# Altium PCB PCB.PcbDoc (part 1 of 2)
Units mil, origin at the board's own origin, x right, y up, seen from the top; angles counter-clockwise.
Board outline 5216.54 x 1820.87 mil, 2 copper layers (Top Layer, Bottom Layer), stack 62 mil thick; 55 components, 32 nets, 136 pads, 25 vias.
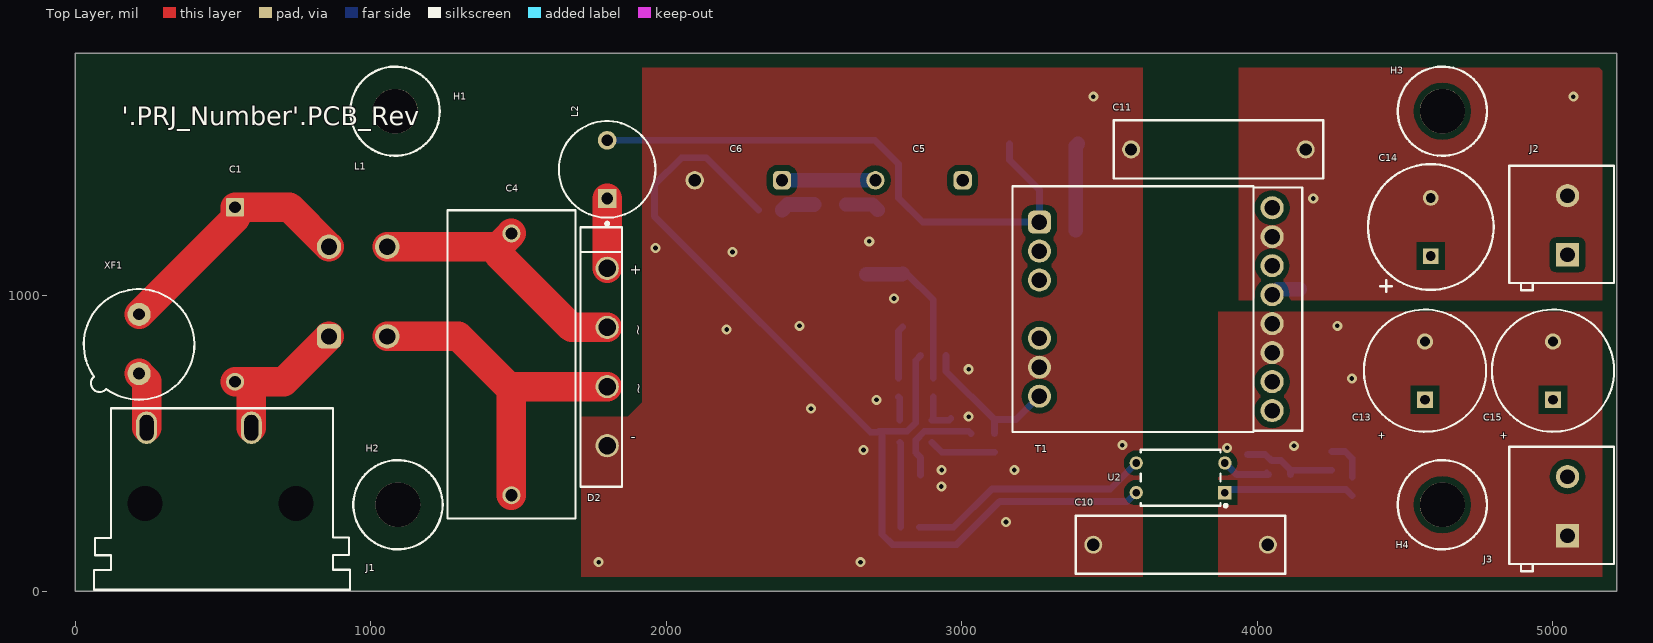
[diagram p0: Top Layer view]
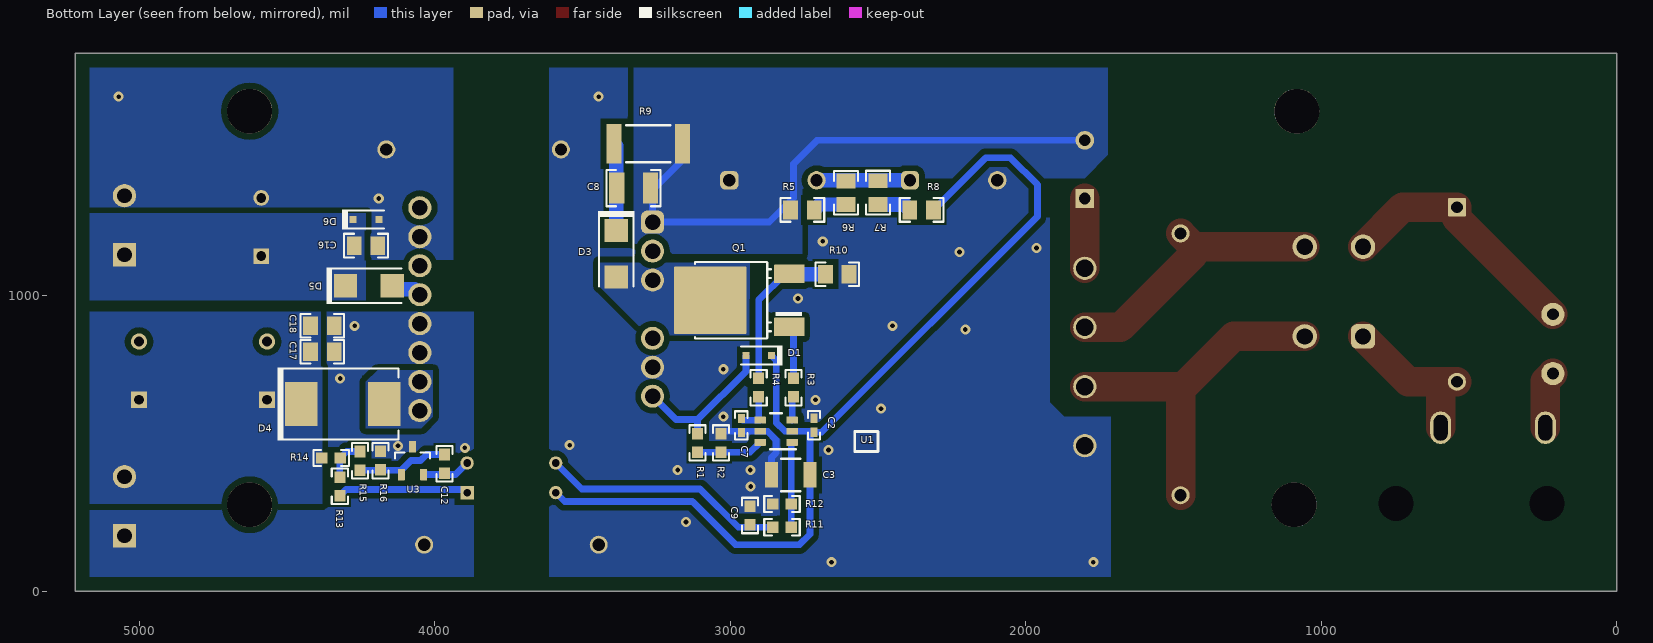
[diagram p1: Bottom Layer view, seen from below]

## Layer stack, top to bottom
Top Solder: solder mask 0.4, Solder Resist, Dk 3.5
Top Layer: signal copper 1.4
Dielectric1: core 59.2, FR-4, Dk 4.8
Bottom Layer: signal copper 1.4
Bottom Solder: solder mask 0.4, Solder Resist, Dk 3.5

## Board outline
0,0 5216.54,0 5216.54,1820.87 0,1820.87

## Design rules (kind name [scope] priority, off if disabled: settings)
AcuteAngle [All] p1: minimum=4.50000000000000E+0001 checktracksonly=FALSE
AssemblyTestPointUsage [All] p1: valid=2
Clearance Clearance_2 [InNetClass('HV') vs Not InNetClass('HV')] p1: gap=60 ignorepadtopadclearanceinfootprint=FALSE
Clearance Clearance_1 [InNetClass('MV') vs Not InNetClass('MV')] p2: gap=30 ignorepadtopadclearanceinfootprint=FALSE
Clearance Clearance_Keepouts [((IsTrack Or IsArc) And Not InPoly) And IsFree and IsKeepOut vs ((IsTrack Or IsArc) And Not InPoly) And IsFree and IsKeepOut] p3: gap=0 ignorepadtopadclearanceinfootprint=FALSE
Clearance Clearance_BoardEdge_MountingHoles [OnCopper and InComponentClass('Mounting Holes') vs IsKeepOut] p4: gap=40 ignorepadtopadclearanceinfootprint=FALSE except(0: Arc-Hole Track-Hole SMDPad-Hole THPad-Hole Via-Hole Fill-Hole Poly-Hole Region-Hole Text-Hole)
Clearance Clearance_BoardEdge_Poly [OnCopper and InPoly vs IsKeepOut] p5: gap=50 ignorepadtopadclearanceinfootprint=FALSE except(0: Arc-Hole Track-Hole SMDPad-Hole THPad-Hole Via-Hole Fill-Hole Poly-Hole Region-Hole Text-Hole)
Clearance Clearance_BoardEdge [OnCopper and Not InComponentClass('Logo') and not InComponentClass('FiducialMark') and not InRegion(1000,500,4000,800) and Not IsKeepout vs IsKeepOut] p6: gap=75 ignorepadtopadclearanceinfootprint=FALSE except(0: Arc-Hole Track-Hole SMDPad-Hole THPad-Hole Via-Hole Fill-Hole Poly-Hole Region-Hole Text-Hole)
Clearance Clearance_Poly [InPolygon] p7: gap=20 ignorepadtopadclearanceinfootprint=FALSE except(0: Arc-Hole Track-Hole SMDPad-Hole THPad-Hole Via-Hole Fill-Hole Poly-Hole Region-Hole Text-Hole)
Clearance [All] p8: gap=7.87 ignorepadtopadclearanceinfootprint=FALSE except(0: Arc-Hole Track-Hole SMDPad-Hole THPad-Hole Via-Hole Fill-Hole Poly-Hole Region-Hole Text-Hole)
ComponentClearance ComponentClearance_MountingHoles_FiducialMarks [InComponentClass('Mounting Holes') vs InComponentClass('FiducialMark')] p1: gap=20 collisioncheckmode=3 verticalgap=10 showdistances=FALSE
ComponentClearance ComponentClearance_Shunt [InComponentClass('Header') vs InComponentClass('Shunt')] p2: gap=0 collisioncheckmode=3 verticalgap=0 showdistances=FALSE
ComponentClearance ComponentClearance_Logo [InComponentClass('Logo')] p3: gap=5 collisioncheckmode=3 verticalgap=10 showdistances=FALSE
ComponentClearance ComponentClearance_ScrewToNut [(HasFootprint('NY PMS 440 0025 PH')) vs (HasFootprint('Keystone_1902C'))] p4: gap=20 collisioncheckmode=3 verticalgap=100000 showdistances=FALSE
ComponentClearance ComponentClearance_MountingHoles [InComponentClass('Mounting Holes')] p5: gap=20 collisioncheckmode=3 verticalgap=10 showdistances=FALSE
ComponentClearance ComponentClearance_SmallPassives [HasFootprint('0201*') or HasFootprint('0402*') or HasFootprint('0508') or HasFootprint('0603*') or HasFootprint('0612') or HasFootprint('0805*') or HasFootprint('0815*') or HasFootprint('0830*') or HasFootprint('1206*') or HasFootprint('1210*') or HasFootprint('1808*') or HasFootprint('1812*') or HasFootprint('1825*') or HasFootprint('2010*') or HasFootprint('2220*') or HasFootprint('2225*') or HasFootprint('2512*') or HasFootprint('2728*') or HasFootprint('3518*') vs HasFootprint('0201*') or HasFootprint('0402*') or HasFootprint('0508') or HasFootprint('0603*') or HasFootprint('0612') or HasFootprint('0805*') or HasFootprint('0815*') or HasFootprint('0830*') or HasFootprint('1206*') or HasFootprint('1210*') or HasFootprint('1808*') or HasFootprint('1812*') or HasFootprint('1825*') or HasFootprint('2010*') or HasFootprint('2220*') or HasFootprint('2225*') or HasFootprint('2512*') or HasFootprint('2728*') or HasFootprint('3518*')] p6: gap=20 collisioncheckmode=3 verticalgap=20 showdistances=FALSE
ComponentClearance ComponentClearance_THtoSMT [IsThruComponent vs IsSMTComponent] p7: gap=10 collisioncheckmode=3 verticalgap=10 showdistances=FALSE
ComponentClearance ComponentClearance_THtoTH [IsThruComponent vs IsThruComponent] p8: gap=10 collisioncheckmode=3 verticalgap=10 showdistances=FALSE
ComponentClearance [All] p9: gap=10 collisioncheckmode=3 verticalgap=10 showdistances=FALSE
DiffPairsRouting [All] p1: maxlimit=100 minlimit=10 mostfreqgap=10 toplayer_minwidth=15 toplayer_maxwidth=15 toplayer_prefwidth=15 bottomlayer_minwidth=15 bottomlayer_maxwidth=15 bottomlayer_prefwidth=15 maxuncoupledlength=1000
FabricationTestPointUsage TestPointUsage [All] p1: valid=2 allowmultiple=FALSE
FabricationTestpoint Testpoint [All] p1: side=3 testpointundercomponent=TRUE minsize=40 maxsize=100 preferedsize=60 minholesize=0 maxholesize=40 preferedholesize=32 testpointgrid=1 allowsidetop=TRUE allowsidebottom=TRUE usegrid=TRUE gridtolerance=0.01
FanoutControl Fanout_LCC [IsLCC] p1: bgadir=Out bgaviamode=Centered fanoutstyle=Auto fanoutdirection=Alternating viagrid=1 // Fanout_LCC (Default Rule)
FanoutControl Fanout_BGA [IsBGA] p2: bgadir=Out bgaviamode=Centered fanoutstyle=Auto fanoutdirection=Alternating viagrid=1 // Fanout_BGA (Default Rule)
FanoutControl Fanout_Default [All] p4: bgadir=Out bgaviamode=Centered fanoutstyle=Auto fanoutdirection=Alternating viagrid=1 // Fanout_Default (Default Rule)
FanoutControl Fanout_Small [(CompPinCount < 5)] p5: bgadir=Out bgaviamode=Centered fanoutstyle=Auto fanoutdirection=OutThenIn viagrid=1 // Fanout_Small (Default Rule)
Height [All] p1: minheight=0 maxheight=3000 prefheight=500
HoleSize [All] p1: absolutevalues=TRUE maxlimit=251 minlimit=7 maxpercent=80.000 minpercent=20.000
MinimumAnnularRing MinimumAnnularRing_ThermalPadVias [IsVia and InAnyComponent] p1: minimumring=5.91
MinimumAnnularRing [All] p2: minimumring=4.9
MinimumSolderMaskSliver MinimumSolderMaskSliver_Logo [InComponentClass('Logo') vs InComponentClass('Logo')] p1: minsoldermaskwidth=0.7
MinimumSolderMaskSliver [All] p2: minsoldermaskwidth=2
PlaneConnect [All] p1: planeconnectstyle=Direct reliefexpansion=10 reliefentries=4 reliefconductorwidth=10 reliefairgap=10
PolygonConnect PolygonConnect_15 [All vs IsNamedPolygon('C109_2') Or  IsNamedPolygon('C107_2') Or  IsNamedPolygon('HV') Or  IsNamedPolygon('Q203_5') Or  IsNamedPolygon('C107_2') Or  IsNamedPolygon('HS') Or  IsNamedPolygon('Q201_5') Or  IsNamedPolygon('Q203_5') Or  IsNamedPolygon('C106_2') Or  IsNamedPolygon('C108_2') Or  IsNamedPolygon('Vout') Or  IsNamedPolygon('Q203_5') Or  IsNamedPolygon('C108_2') Or  IsNamedPolygon('C113_2') Or  IsNamedPolygon('Q203_5') Or  IsNamedPolygon('Q201_5') Or  IsNamedPolygon('C107_2') Or  IsNamedPolygon('C102_1') Or  IsNamedPolygon('SGND') Or  IsNamedPolygon('GND') Or  IsNamedPolygon('SGND') Or  IsNamedPolygon('GND') Or  IsNamedPolygon('IN+') Or  IsNamedPolygon('IN+') Or  IsNamedPolygon('Q201_5') Or  IsNamedPolygon('Q201_5') Or  IsNamedPolygon('SGND') Or  IsNamedPolygon('SGND') Or  IsNamedPolygon('Vout') Or  IsNamedPolygon('Vout') Or  IsNamedPolygon('IN+') Or  IsNamedPolygon('GND') Or  IsNamedPolygon('IN+') Or  IsNamedPolygon('GND')] p1: connectstyle=Direct reliefconductorwidth=10 reliefentries=4 polygonreliefangle="90 Angle" airgapwidth=10
PolygonConnect PolygonConnect_14 [All vs IsNamedPolygon('C106_2') Or  IsNamedPolygon('C107_2') Or  IsNamedPolygon('C107_2') Or  IsNamedPolygon('C107_2') Or  IsNamedPolygon('C102_1') Or  IsNamedPolygon('Q203_5') Or  IsNamedPolygon('Vout') Or  IsNamedPolygon('Q203_5') Or  IsNamedPolygon('Q203_5') Or  IsNamedPolygon('Q201_5') Or  IsNamedPolygon('C108_2') Or  IsNamedPolygon('Q203_5') Or  IsNamedPolygon('HS') Or  IsNamedPolygon('HV') Or  IsNamedPolygon('C108_2') Or  IsNamedPolygon('Q201_5') Or  IsNamedPolygon('C109_2') Or  IsNamedPolygon('Q201_5') Or  IsNamedPolygon('Q201_5') Or  IsNamedPolygon('C113_2')] p2: connectstyle=Direct reliefconductorwidth=10 reliefentries=4 polygonreliefangle="90 Angle" airgapwidth=10
PolygonConnect PolygonConnect_13 [All vs IsNamedPolygon('C102_1') Or  IsNamedPolygon('HV') Or  IsNamedPolygon('C107_2') Or  IsNamedPolygon('C109_2') Or  IsNamedPolygon('C107_2') Or  IsNamedPolygon('C108_2') Or  IsNamedPolygon('C106_2') Or  IsNamedPolygon('C108_2') Or  IsNamedPolygon('C113_2') Or  IsNamedPolygon('C107_2')] p3: connectstyle=Direct reliefconductorwidth=10 reliefentries=4 polygonreliefangle="90 Angle" airgapwidth=10
PolygonConnect PolygonConnect_12 [All vs IsNamedPolygon('C107_2') Or  IsNamedPolygon('C113_2') Or  IsNamedPolygon('C106_2') Or  IsNamedPolygon('C107_2') Or  IsNamedPolygon('C107_2') Or  IsNamedPolygon('C102_1')] p4: connectstyle=Direct reliefconductorwidth=10 reliefentries=4 polygonreliefangle="90 Angle" airgapwidth=10
PolygonConnect PolygonConnect_11 [All vs IsNamedPolygon('C106_2') Or  IsNamedPolygon('C102_1') Or  IsNamedPolygon('C107_2') Or  IsNamedPolygon('C107_2') Or  IsNamedPolygon('C107_2')] p5: connectstyle=Direct reliefconductorwidth=10 reliefentries=4 polygonreliefangle="90 Angle" airgapwidth=10
PolygonConnect PolygonConnect_10 [All vs IsNamedPolygon('C106_2')] p6: connectstyle=Direct reliefconductorwidth=10 reliefentries=4 polygonreliefangle="90 Angle" airgapwidth=10
PolygonConnect PolygonConnect_9 [All vs IsNamedPolygon('C11_1') Or  IsNamedPolygon('Vin') Or  IsNamedPolygon('Vin') Or  IsNamedPolygon('5V') Or  IsNamedPolygon('D6_2') Or  IsNamedPolygon('Q3_3') Or  IsNamedPolygon('GND2') Or  IsNamedPolygon('GND2') Or  IsNamedPolygon('GND') Or  IsNamedPolygon('Q3_4') Or  IsNamedPolygon('12V5') Or  IsNamedPolygon('GND') Or  IsNamedPolygon('12V5') Or  IsNamedPolygon('D3_1')] p7: connectstyle=Direct reliefconductorwidth=10 reliefentries=4 polygonreliefangle="90 Angle" airgapwidth=10
PolygonConnect PolygonConnect_8 [All vs IsNamedPolygon('C11_1') Or  IsNamedPolygon('Vin') Or  IsNamedPolygon('12V5') Or  IsNamedPolygon('Q3_3') Or  IsNamedPolygon('GND2') Or  IsNamedPolygon('GND2') Or  IsNamedPolygon('5V') Or  IsNamedPolygon('Q3_4') Or  IsNamedPolygon('12V5')] p8: connectstyle=Direct reliefconductorwidth=10 reliefentries=4 polygonreliefangle="90 Angle" airgapwidth=10
PolygonConnect PolygonConnect_7 [All vs IsNamedPolygon('GND2') Or  IsNamedPolygon('GND2') Or  IsNamedPolygon('5V') Or  IsNamedPolygon('12V5') Or  IsNamedPolygon('12V5') Or  IsNamedPolygon('C11_1')] p9: connectstyle=Direct reliefconductorwidth=10 reliefentries=4 polygonreliefangle="90 Angle" airgapwidth=10
PolygonConnect PolygonConnect_6 [All vs IsNamedPolygon('GND2') Or  IsNamedPolygon('SGND') Or  IsNamedPolygon('GND1') Or  IsNamedPolygon('C901_1') Or  IsNamedPolygon('SGND') Or  IsNamedPolygon('GND2') Or  IsNamedPolygon('GND1')] p10: connectstyle=Direct reliefconductorwidth=10 reliefentries=4 polygonreliefangle="90 Angle" airgapwidth=10
PolygonConnect PolygonConnect_5 [All vs IsNamedPolygon('GND1') Or  IsNamedPolygon('GND1')] p11: connectstyle=Direct reliefconductorwidth=10 reliefentries=4 polygonreliefangle="90 Angle" airgapwidth=10
PolygonConnect PolygonConnect_4 [All vs IsNamedPolygon('C21_1') Or  IsNamedPolygon('C5_1') Or  IsNamedPolygon('C12_2') Or  IsNamedPolygon('C2_2') Or  IsNamedPolygon('C13_1') Or  IsNamedPolygon('C28_1') Or  IsNamedPolygon('C6_1') Or  IsNamedPolygon('GND') Or  IsNamedPolygon('GND2') Or  IsNamedPolygon('C14_1') Or  IsNamedPolygon('C13_1') Or  IsNamedPolygon('Q1_3') Or  IsNamedPolygon('C14_1') Or  IsNamedPolygon('C5_1') Or  IsNamedPolygon('GND2') Or  IsNamedPolygon('C28_1') Or  IsNamedPolygon('D5_2') Or  IsNamedPolygon('D6_2') Or  IsNamedPolygon('D2_1') Or  IsNamedPolygon('C12_2') Or  IsNamedPolygon('D2_1') Or  IsNamedPolygon('C4_1') Or  IsNamedPolygon('C4_1') Or  IsNamedPolygon('C2_2') Or  IsNamedPolygon('GND') Or  IsNamedPolygon('C33_1') Or  IsNamedPolygon('C9_1')] p12: connectstyle=Direct reliefconductorwidth=10 reliefentries=4 polygonreliefangle="90 Angle" airgapwidth=10
PolygonConnect PolygonConnect_3 [All vs IsNamedPolygon('C28_1') Or  IsNamedPolygon('C12_2') Or  IsNamedPolygon('C28_1') Or  IsNamedPolygon('C9_1') Or  IsNamedPolygon('D5_2') Or  IsNamedPolygon('C12_2') Or  IsNamedPolygon('C2_2') Or  IsNamedPolygon('C14_1') Or  IsNamedPolygon('C4_1') Or  IsNamedPolygon('C14_1') Or  IsNamedPolygon('D6_2') Or  IsNamedPolygon('GND2') Or  IsNamedPolygon('Q1_3') Or  IsNamedPolygon('C5_1') Or  IsNamedPolygon('D2_1') Or  IsNamedPolygon('C4_1') Or  IsNamedPolygon('C13_1') Or  IsNamedPolygon('C5_1') Or  IsNamedPolygon('C13_1') Or  IsNamedPolygon('C33_1') Or  IsNamedPolygon('D2_1') Or  IsNamedPolygon('GND') Or  IsNamedPolygon('GND') Or  IsNamedPolygon('GND2') Or  IsNamedPolygon('C2_2') Or  IsNamedPolygon('C6_1') Or  IsNamedPolygon('C21_1')] p13: connectstyle=Direct reliefconductorwidth=10 reliefentries=4 polygonreliefangle="90 Angle" airgapwidth=10
PolygonConnect PolygonConnect_2 [All vs IsNamedPolygon('C21_1') Or  IsNamedPolygon('C4_1') Or  IsNamedPolygon('D5_2') Or  IsNamedPolygon('C5_1') Or  IsNamedPolygon('C14_1') Or  IsNamedPolygon('C13_1') Or  IsNamedPolygon('C4_1') Or  IsNamedPolygon('C33_1') Or  IsNamedPolygon('C12_2') Or  IsNamedPolygon('D2_1') Or  IsNamedPolygon('C2_2') Or  IsNamedPolygon('C28_1') Or  IsNamedPolygon('C12_2') Or  IsNamedPolygon('D2_1') Or  IsNamedPolygon('C5_1') Or  IsNamedPolygon('Q1_3') Or  IsNamedPolygon('GND') Or  IsNamedPolygon('D6_2') Or  IsNamedPolygon('C6_1') Or  IsNamedPolygon('C2_2') Or  IsNamedPolygon('C14_1') Or  IsNamedPolygon('C28_1') Or  IsNamedPolygon('C13_1') Or  IsNamedPolygon('C9_1') Or  IsNamedPolygon('GND')] p14: connectstyle=Direct reliefconductorwidth=10 reliefentries=4 polygonreliefangle="90 Angle" airgapwidth=10
PolygonConnect PolygonConnect_1 [All vs IsNamedPolygon('C28_1') Or  IsNamedPolygon('D5_2') Or  IsNamedPolygon('C5_1') Or  IsNamedPolygon('C5_1') Or  IsNamedPolygon('D2_1') Or  IsNamedPolygon('C21_1') Or  IsNamedPolygon('C9_1') Or  IsNamedPolygon('C4_1') Or  IsNamedPolygon('C14_1') Or  IsNamedPolygon('C28_1') Or  IsNamedPolygon('C6_1') Or  IsNamedPolygon('C12_2') Or  IsNamedPolygon('C33_1') Or  IsNamedPolygon('C4_1') Or  IsNamedPolygon('C13_1') Or  IsNamedPolygon('C12_2') Or  IsNamedPolygon('D6_2') Or  IsNamedPolygon('C2_2') Or  IsNamedPolygon('C14_1') Or  IsNamedPolygon('D2_1') Or  IsNamedPolygon('C2_2') Or  IsNamedPolygon('C13_1')] p15: connectstyle=Direct reliefconductorwidth=10 reliefentries=4 polygonreliefangle="90 Angle" airgapwidth=10
PolygonConnect [All] p16: connectstyle=Direct reliefconductorwidth=10 reliefentries=4 polygonreliefangle="90 Angle" airgapwidth=10
RoutingVias ThermalPadVias [IsVia and InAnyComponent] p1: holewidth=7.87 width=19.68 viastyle="Through Hole" minholewidth=7.87 minwidth=19.68 maxholewidth=12.99 maxwidth=23.62
RoutingVias [All] p2: holewidth=16 width=34 viastyle="Through Hole" minholewidth=7.87 minwidth=20 maxholewidth=40 maxwidth=65
SilkToBoardRegionClearance [Not ((IsComment or IsDesignator) And (Hide <> 'False')) and not InRegion(1000,500,4000,800)] p1:
SilkToSilkClearance SilkToSilkClearance_Pb-FreeLogo [(HasFootprint('Pb-Free_Overlay_Medium') OR HasFootprint('Pb-Free_Overlay_Small')) vs (HasFootprint('Pb-Free_Overlay_Medium') OR HasFootprint('Pb-Free_Overlay_Small'))] p1: silktosilkclearance=0
SilkToSilkClearance [All] p2: silktosilkclearance=1
SilkToSolderMaskClearance "Silk to Solder Mask Opening" [All] p1: minsilkscreentomaskgap=1 clearancetoexposedcopper=FALSE
SolderMaskExpansion [All] p1: expansion=1.97
Width [All] p1: maxlimit=100 minlimit=6 preferedwidth=10 checkconnectedcopper=TRUE
14 further rules are at their usual default settings.

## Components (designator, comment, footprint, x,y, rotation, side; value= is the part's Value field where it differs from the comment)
C1 "B32642B0223J" FP-B32642B0223J_RADIAL-MFG 541.34,1003.94 r270 top value=0.022µF
C2 "GCM155R71H104KE02D" 0402 2716.54,561.74 r90 bottom value=0.1uF
C3 "C1210C226K3RAC7800" 1210_280 2795.28,393.7 r0 bottom value=22uF
C4 "B32653A224J189" B32653_2650x2050x1100 1476.38,767.72 r90 top value=0.22uF
C5 "400BXW68MEFR14.5X30" BXW_1450x3000_HU 2855.32,1390.38 r180 top value=68uF
C6 "400BXW68MEFR14.5X30" BXW_1450x3000_HU 2244.09,1390.38 r180 top value=68uF
C7 "GRM1555C1H270JA01D" 0402 2962.6,561.02 r270 bottom value=27pF
C8 "VJ1210Y472KXGAT5Z" 1210 3326.77,1364.15 r0 bottom value=4700pF
C9 "GRM188R71H221KA01D" 0603 2933.07,256.27 r90 bottom value=220pF
C10 "B32652A0103K" B32652A_500x1050x1800 3740.16,157.48 r180 top value=0.01uF
C11 "B32652A0103K" B32652A_500x1050x1800 3868.11,1494.86 r180 top value=0.01uF
C12 "GRM188R71E153KA01D" 0603 3966.53,431.27 r270 bottom value=0.015uF
C13 "6.3ZLJ2700M10X20" ZLJ_1000X2000 4566.93,746.23 r90 top value=2700uF
C14 "25ZLJ470M10X12.5" ZLJ_1000x1250 4586.61,1232.26 r90 top value=470uF
C15 "6.3ZLJ2700M10X20" ZLJ_1000X2000 5000,746.23 r90 top value=2700uF
C16 "B37941K9105K62" 0805_HV 4232.28,1169.46 r180 bottom value=1uF
C17 "B37941K9105K62" 0805_HV 4379.92,810.43 r180 bottom value=1uF
C18 "B37941K9105K62" 0805_HV 4379.92,898.17 r180 bottom value=1uF
D1 "BAS316,115" SOD-323 2903.54,797.24 r0 bottom value=100V
D2 "GBU4K-E3/51" GBU 1800.17,792.52 r270 top value=800V
D3 "US1K-13-F" SMA 3385.83,1141.73 r270 bottom value=800V
D4 "B3100-13-F" SMC 4311.02,633.26 r180 bottom value=100V
D5 "STPS1150A" SMA 4222.44,1033.46 r180 bottom value=150V
D6 "BZX384-C15,115" SOD-323 4232.28,1258.04 r180 bottom value=15V
H1 "4826" KEYSTONE_4826 1082.68,1624.02 r0 top
H2 "4826" KEYSTONE_4826 1092.52,292.69 r0 top
H3 "4826" KEYSTONE_4826 4625.98,1624.02 r0 top
H4 "4826" KEYSTONE_4826 4625.98,292.69 r0 top
J1 "770W-X2/10" CONN_AC_770W-SERIES 492.13,423.23 r180 top
J2 "ED120/2DS" On-Shore_ED120_2DS 5049.21,1238.36 r90 top
J3 "ED120/2DS" On-Shore_ED120_2DS 5049.21,287.77 r90 top
L1 "750318019" Wurth_750318019 957.52,1013.78 r90 top value=850uH
L2 "768772102" WE-TI_8095 1800.17,1427.17 r90 top value=1mH
Q1 "FQD2N100TM" DPAK 2933.88,984.25 r0 bottom value=1000V
R1 "CRCW060338K3FKEA" 0603 3110.24,501.75 r90 bottom value=38.3k
R2 "CRCW06036K04FKEA" 0603 3031.5,501.75 r270 bottom value=6.04k
R3 "CRCW060310R0FKEA" 0603 2785.43,688.96 r90 bottom value=10.0
R4 "CRCW0603787RFKEA" 0603 2903.54,688.96 r90 bottom value=787
R5 "CRCW0805470KJNEA" 0805_HV 2755.91,1289.98 r0 bottom value=470k
R6 "CRCW0805470KJNEA" 0805_HV 2608.27,1348.43 r270 bottom value=470k
R7 "CRCW0805470KJNEA" 0805_HV 2500,1348.74 r90 bottom value=470k
R8 "CRCW0805470KJNEA" 0805_HV 2352.36,1289.98 r0 bottom value=470k
R9 "CRCW25128K20JNEG" 2512 3277.19,1513.95 r180 bottom value=8.2k
R10 "RC0805FR-071R21L" 0805_HV 2637.8,1072.83 r0 bottom value=1.21
R11 "CRCW060378K7FKEA" 0603 2824.8,216.54 r0 bottom value=78.7k
R12 "CRCW06034K02FKEA" 0603 2824.8,295.28 r180 bottom value=4.02k
R13 "CRCW0603750RFKEA" 0603 4320.86,354.63 r90 bottom value=750
R14 "CRCW06030000Z0EA" 0603 4350.39,450.95 r0 bottom value=0
R15 "CRCW060390K9FKEA" 0603 4251.96,441.11 r90 bottom value=90.9k
R16 "CRCW060340K2FKEA" 0603 4183.07,441.97 r270 bottom value=40.2k
T1 "750317656" Wurth_EE20-10-6_5643 3656.32,954.31 r0 top
U1 "UCC28742DBVR" DBV0006A_N 2844.49,541.34 r0 bottom
U2 "FOD817A" DIP-4 3740.16,383.86 r180 top
U3 "TLV431ACDBZR" DBZ0003A_N 4074.8,441.97 r90 bottom
XF1 "56000001009" FuseHolder_560000010 216.54,836.61 r270 top value=TR5

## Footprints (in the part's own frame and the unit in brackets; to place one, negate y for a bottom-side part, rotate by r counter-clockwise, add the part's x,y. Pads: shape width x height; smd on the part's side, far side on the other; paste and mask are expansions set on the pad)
0402 [mm] "0402 from SM-752 data"
  rect 0.8x0.6 smd: 1(-0.6,0) 2(0.6,0)
  silkscreen extent -1.22,-0.52 1.22,0.52, body extent -0.55,-0.3 0.55,0.3, height 0.6
0603 [mm] "0603 from SM-752 data"
  rect 1x0.95 smd: 1(-0.8,0) 2(0.8,0)
  silkscreen extent -1.52,-0.69 1.52,0.69, body extent -0.87,-0.47 0.87,0.47, height 1
0805_HV [mil] "0805 with 30mil clearance between pads"
  rect 50x63 smd: 1(-40,0) 2(40,0)
  silkscreen extent -74,-40 74,40, body extent -43,-29 43,29, height 57
1210 [mm] "1210 from SM-752 data"
  rect 1.3x2.7 smd: 1(-1.45,0) 2(1.45,0)
  silkscreen extent -2.32,-1.57 2.32,1.57, body extent -1.7,-1.35 1.7,1.35, height 1.35
1210_280 [mm] "SMD, 2-Leads, Body 3.6x2.8mm, Height 2.8mm"
  rect 1.1x2.2 smd: 1(-1.65,0) 2(1.65,0)
  silkscreen extent -0.84,-1.4 0.84,1.4, body extent -1.8,-1.4 1.8,1.4, height 2.8
2512 [mm] "Chip Resistor, Body 6.3x3.2mm, IPC Medium Density"
  rect 1.3x3.4 smd: 1(-2.95,0) 2(2.95,0)
  silkscreen extent -1.9,-1.6 1.9,1.6, body extent -3.22,-1.67 3.22,1.67, height 0.71
B32652A_500x1050x1800 [mm] "THD, 2-Leads, Body 18x5mm, Height 10.5mm"
  round 1.55 hole 1.05: 1(-7.5,0) 2(7.5,0)
  silkscreen extent -9,-2.5 9,2.5, body extent -9,-2.5 9,2.5, height 10.5
B32653_2650x2050x1100 [mm] "TH, 2-Leads, Body 26.5x11mm, Pin Spacing 22.5mm"
  round 1.55 hole 1.05: 1(-11.25,0) 2(11.25,0)
  silkscreen extent -13.25,-5.5 13.25,5.5, body extent -13.25,-5.5 13.25,5.5, height 20.5
BXW_1450x3000_HU [mm] "TH, 2-Leads, Dia 14.5mm, Pin Spacing 7.5mm"
  rrect50% 1.575x1.575 hole 1.05: 1(-3.75,0)
  round 1.575 hole 1.05: 2(3.75,0)
  body extent -7.5,-0.4 7.5,34.55, height 15
CONN_AC_770W-SERIES [mm] "Qualtek Electronics"
  oval 1.8x2.8 hole 1.2 slot 2.2 at 90 deg: 1(6.35,-3.3) 2(-2.65,-3.3)
  round 2 hole 3 unplated: MH1(6.5,3.2) MH2(-6.5,3.2)
  silkscreen extent -11.12,-4.97 10.87,10.63, body extent -11.05,-4.8 10.8,10.6, height 22
DBV0006A_N [mm] "SOT23, 6-Leads, Body 2.9x1.6mm, Pitch 0.95mm, Lead Span 2.8mm, IPC Medium Density"
  rrect17% 1x0.6 smd: 1(-1.375,0.95) 2(-1.375,0) 3(-1.375,-0.95) 4(1.375,-0.95) 5(1.375,0) 6(1.375,0.95)
  silkscreen extent -1.68,-1.55 0.5,1.55, body extent -1.42,-1.46 1.42,1.46, height 1.12
DBZ0003A_N [mm] "SOT23, 3-Leads, Body 2.9x1.3mm, Pitch 0.95mm, Lead Span 2.4mm, IPC Medium Density"
  rrect17% 1x0.6 smd: 1(-1.2,0.95) 2(-1.2,-0.95) 3(1.2,0)
  silkscreen extent 0.2,-1.5 0.7,1.5, body extent -1.26,-1.46 1.26,1.46, height 0.98
DIP-4 [mm] "DIP, 4-Leads, Body 6.86x4.83mm, Pitch 2.54mm"
  rect 1.15x1.15 hole 0.65: 1(-3.81,1.27)
  round 1.15 hole 0.65: 2(-3.81,-1.27) 3(3.81,-1.27) 4(3.81,1.27)
  silkscreen extent -4,-2.41 3.43,2.52, body extent -4.02,-2.42 4.02,2.41, height 5.59
DPAK [mm] "D-PAK, 3-Pads, Body 6.22x6.73mm (max), TO-252AA using nominal STEP model"
  rrect6% 2.6x1.6 smd: 1(-3.4,2.28) 3(-3.4,-2.28)
  rrect2% 6.2x5.8 smd paste-2.9: 4(3.4,0)
  silkscreen extent -4.5,-3.3 4.7,3.28, body extent -3.86,-3.29 5.84,3.29, height 2.48
FP-B32642B0223J_RADIAL-MFG [mm]
  rrect6% 1.55x1.55 hole 1 paste-1000 mask+0: 1(-7.5,0)
  round 1.55 hole 1 paste-1000 mask+0: 2(7.5,0)
  body extent -9.1,-3.1 9.1,3.1, height 0.25
FuseHolder_560000010 [mm] "Littelfuse fuse holder TR5"
  round 2 hole 1: 1(-2.54,0) 2(2.54,0)
  silkscreen extent -4.71,-4.75 4.79,4.75, body extent -4.75,-4.74 4.75,4.75, height 5.6
GBU [mm] "Comchip / Diodes Inc diode bridge"
  round 2 hole 1.5: 1(-7.62,0) 2(-2.54,0) 3(2.54,0) 4(7.62,0)
  silkscreen extent -11.15,-2.28 11.15,1.28, body extent -11.15,-2.28 11.15,1.28, height 21.55
KEYSTONE_4826 [mil] "HEX STANDOFF 6-32 NYLON 1750 mil"
  round 1 on Mech3: 0(0,0)
  round 152 hole 152 unplated: MH(0,0)
  silkscreen extent -151,-151 151,151, body extent -144,-125 144,125, height 1751
On-Shore_ED120_2DS [mm] "ONSHORE"
  rrect5% 2x2 hole 1.25: 1(-2.54,0)
  round 2 hole 1.25: 2(2.54,0)
  silkscreen extent -5.6,-4 5.12,5, body extent -5.78,-4 5.08,5, height 13
SMA [mm] "Molded Diode, 2-Leads, Body 4.3x2.6mm, IPC Medium Density, based on OnSemi component dimensions and land pattern"
  rect 2x2 smd: 1(-2,0) 2(2,0)
  silkscreen extent -3.66,-1.57 2.79,1.57, body extent -2.6,-1.3 2.6,1.3, height 2.42
SMC [mil] "Molded Diode, 2-Leads, Body 6.9x5.8mm, IPC Medium Density, based on OnSemi component dimensions and land patterns"
  rect 110x150 smd: 1(-140.49,0) 2(140.49,0)
  silkscreen extent -221,-123 189,124, body extent -156,-116 157,116, height 91
SOD-323 [mm] "NXP recommended land pattern"
  rect 0.6x0.6 smd paste-0.05: 1(-1.1,0) 2(1.1,0)
  silkscreen extent -2.06,-0.86 1.53,0.86, body extent -1.3,-0.67 1.3,0.68, height 1.1
WE-TI_8095 [mm] "Wurth WE-TI 8095"
  rect 1.6x1.6 hole 1: 1(-2.5,0)
  round 1.6 hole 1: 2(2.5,0)
  silkscreen extent -4.79,-4.15 4.15,4.15, body extent -4.12,-4.14 4.15,4.14, height 10
Wurth_750318019 [mm] "TH, 4-Leads, Body 18.5x14.5mm"
  rrect50% 2.1x2.1 hole 1.4: 1(-3.85,2.5)
  round 2.1 hole 1.4: 2(-3.85,-2.5) 3(3.85,-2.5) 4(3.85,2.5)
  body extent -9.25,-7.25 9.25,7.25, height 21.72
Wurth_EE20-10-6_5643 [mm] "TH, 14-Leads, Body 25x22.2mm"
  rrect50% 1.98x1.98 hole 1.32: 1(-10,7.48)
  round 1.98 hole 1.32: 2(-10,4.99) 3(-10,2.5) 4(-10,-2.5) 5(-10,-4.99) 6(-10,-7.48) 7(10,-8.715) 8(10,-6.225) 9(10,-3.735) 10(10,-1.245) 11(10,1.245) 12(10,3.735) 13(10,6.225) 14(10,8.715)
  silkscreen extent -12.32,-10.55 12.58,10.57, body extent -12.32,-10.55 12.66,10.57, height 15.4
ZLJ_1000x1250 [mm] "Radial, 2-Leads, Dia 10mm, Height 12mm, Pin Spacing 5mm"
  rect 1.35x1.35 hole 0.85 paste+0: 1(-2.5,0)
  round 1.35 hole 0.85 paste+0: 2(2.5,0)
  silkscreen extent -5.58,-5.4 5.4,5.4, body extent -5.36,-5.39 5.39,5.39, height 14.51
ZLJ_1000X2000 [mm] "Rubycon"
  rect 1.4x1.4 hole 0.838: 1(-2.5,0)
  round 1.4 hole 0.838: 2(2.5,0)
  silkscreen extent -5.25,-5.25 5.25,5.25, body extent -5.21,-5.24 5.24,5.24, height 22.01

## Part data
C1: library part CMP-0086383-2, "0.022µF Film Capacitor 600V 1000V (1kV) Polypropylene (PP), Metallized Radial", Manufacturer=TDK, Tolerance_%=5%, VoltageRating=1kV
C2: library part CMP-0006356-2, "CAP, CERM, 0.1 uF, 50 V, +/- 10%, X7R, AEC-Q200 Grade 1, 0402", Cap_Case=0402, Manufacturer=MuRata, Supplier Part Number 1=490-10672-1-ND, TempCo=X7R, Tolerance_%=10%, Value1=Unknown, Value2=50V, ValueDisplayed=0.1uF
C3: library part CMP-0082266-1, "CAP, CERM, 22 µF, 25 V,+/- 10%, X7R, 1210", Cap_Case=1210, Manufacturer=Kemet, Supplier Part Number 1=399-11958-1-ND, TempCo=X7R, Tolerance_%=10%, Value1="0.001 ohm", Value2=25V, ValueDisplayed=22µF
C4: library part CMP-0012347-3, "CAP, Film, 0.22 uF, 1000 V, +/- 5%, TH", Cap_Case=26.5x20.5x11mm, Manufacturer=TDK, Supplier Part Number 1=B32653A224J189-ND, Tolerance_%=5%, Value1=Unknown, Value2=1000V, ValueDisplayed=0.22uF
C5 C6: library part CMP-0750100-2, "CAP, AL, 68 µF, 400 V, +/- 20%, TH", Cap_Case=14.5x30mm, Manufacturer=Rubycon, Tolerance_%=20%, Value2=400V, ValueDisplayed=68µF
C7: library part CMP-0006443-2, "CAP, CERM, 27 pF, 50 V, +/- 5%, C0G/NP0, 0402", Cap_Case=0402, Manufacturer=MuRata, Supplier Part Number 1=14T3294, TempCo=C0G/NP0, Tolerance_%=5%, Value1=Unknown, Value2=50V, ValueDisplayed=27pF
C8: library part CMP-0009286-2, "CAP, CERM, 4700 pF, 1000 V, +/- 10%, X7R, 1210", Cap_Case=1210, Manufacturer=Vishay-Vitramon, Supplier Part Number 1=720-1057-1-ND, TempCo=X7R, Tolerance_%=10%, Value1=Unknown, Value2=1000V, ValueDisplayed=4700pF
C9: library part CMP-0007442-5, "CAP, CERM, 220 pF, 50 V, +/- 10%, X7R, 0603", Cap_Case=0603, Manufacturer=MuRata, Supplier Part Number 1=490-1483-1-ND, TempCo=X7R, Tolerance_%=10%, Value1=Unknown, Value2=50V, ValueDisplayed=220pF
C10 C11: library part CMP-0012344-3, "CAP, Film, 0.01 uF, 1000 V, +/- 10%, TH", Cap_Case=5x10.5x18, Manufacturer=TDK, Tolerance_%=10%, Value1=Unknown, Value2=1000V, ValueDisplayed=0.01uF
C12: library part CMP-0007410-5, "CAP, CERM, 0.015 uF, 25 V, +/- 10%, X7R, 0603", Cap_Case=0603, Manufacturer=MuRata, Supplier Part Number 1=81-GRM39X153K25D, TempCo=X7R, Tolerance_%=10%, Value1=Unknown, Value2=25V, ValueDisplayed=0.015uF
C13 C15: library part CMP-0084270-1, "CAP, AL, 2700 µF, 6.3 V, +/- 20%, TH", Cap_Case=10x20mm, Manufacturer=Rubycon, Tolerance_%=20%, Value2=6.3V, ValueDisplayed=2700µF
C14: library part CMP-0010295-1, "CAP, AL, 470 uF, 25 V, +/- 20%, 0.053 ohm, TH", Cap_Case=10x12.5, Manufacturer=Rubycon, Supplier Part Number 1=1189-1253-ND, Tolerance_%=20%, Value1="0.053 ohm", Value2=25V, ValueDisplayed=470uF
C16 C17 C18: library part CMP-0007697-2, "CAP, CERM, 1 uF, 16 V, +/- 10%, X7R, 0805", Cap_Case=0805, Manufacturer=TDK, Supplier Part Number 1=495-1935-1-ND, TempCo=X7R, Tolerance_%=10%, Value1=Unknown, Value2=16V, ValueDisplayed=1uF
D1: library part CMP-0029006-1, "Diode, Ultrafast, 100 V, 0.25 A, SOD-323", Manufacturer=Nexperia, Supplier Part Number 1=568-5003-1-ND, Value1=0.25A, Value2=1.4V
D2: library part CMP-0029237-3, "Diode, Switching-Bridge, 800 V, 3 A, TH", Manufacturer=Vishay-Semiconductor, Value1=3A, Value2=1V
D3: library part CMP-0076980-1, "Diode, Fast Rectifier, 800 V, 1 A, SMA", Manufacturer="Diodes Inc.", Supplier Part Number 1=US1K-FDICT-ND, Value1=1A, Value2=1.7V
D4: library part CMP-0028411-1, "Diode, Schottky, 100 V, 3 A, SMC", Manufacturer="Diodes Inc.", Supplier Part Number 1=B3100-FDICT-ND, Value1=3A, Value2=0.79V
D5: library part CMP-0028752-1, "Diode, Schottky, 150 V, 1 A, SMA", Manufacturer=STMicroelectronics, Supplier Part Number 1=497-7545-1-ND, Value1=1A, Value2=0.78V
D6: library part CMP-0005844-2, "Diode, Zener, 15 V, 300 mW, SOD-323", Manufacturer="NXP Semiconductor", Power_W=300mW, Supplier Part Number 1=568-6280-1-ND, Value1=0.3W
H1 H2 H3 H4: library part CMP-0003686-1, Manufacturer=Keystone, Supplier Part Number 1=36-4826-ND
J1: library part CMP-0074930-1, "AC Receptacle, 2.5A, R/A, TH", Manufacturer="Qualtek Electronics Corporation", Supplier Part Number 1=Q273-ND
J2 J3: library part CMP-0074910-1, "Terminal Block, 5.08 mm, 2x1, Brass, TH", Color=Blue, Current_A=15A, Manufacturer="On-Shore Technology", Supplier Part Number 1=ED1609-ND, Voltage_V=300V
L1: library part CMP-0086067-1, "Coupled inductor, 850 µH, 0.0154 ohm, TH", Manufacturer="Wurth Elektronik", ValueDisplayed=850µH
L2: library part CMP-0064846-1, "Inductor, Shielded Drum Core, Metal Composite, 1 mH, 0.5 A, 1.7 ohm, TH", Manufacturer="Wurth Elektronik", Supplier Part Number 1=732-3261-ND, Value1="1.7 ohm", Value2=0.5A, ValueDisplayed=1mH
Q1: library part CMP-0001290-1, "MOSFET, N-CH, 1000 V, 1.6 A, DPAK", Alternate Manufacturer=None, Manufacturer="Fairchild Semiconductor", Supplier Part Number 1=FQD2N100TMCT-ND, Value2="12 nC"
R1: library part CMP-0022364-4, "RES, 38.3 k, 1%, 0.1 W, AEC-Q200 Grade 0, 0603", Manufacturer=Vishay-Dale, Power_W=100mW, Supplier Part Number 1=541-38.3KHCT-ND, TempCo="100 ppm/C", Tolerance_%=1%, Value2=0.1W, Value_Code=38k3, ValueDisplayed=38.3k
R2: library part CMP-0022558-4, "RES, 6.04 k, 1%, 0.1 W, AEC-Q200 Grade 0, 0603", Manufacturer=Vishay-Dale, Power_W=100mW, Supplier Part Number 1=541-6.04KHCT-ND, TempCo="100 ppm/C", Tolerance_%=1%, Value2=0.1W, Value_Code=6k04, ValueDisplayed=6.04k
R3: library part CMP-0022003-4, "RES, 10.0, 1%, 0.1 W, AEC-Q200 Grade 0, 0603", Manufacturer=Vishay-Dale, Power_W=100mW, Supplier Part Number 1=541-10.0HCT-ND, TempCo="100 ppm/C", Tolerance_%=1%, Value2=0.1W, Value_Code=10R0, ValueDisplayed=10.0
R4: library part CMP-0022596-5, "RES, 787, 1%, 0.1 W, AEC-Q200 Grade 0, 0603", Manufacturer=Vishay-Dale, Power_W=100mW, Supplier Part Number 1=541-787HCT-ND, TempCo="100 ppm/C", Tolerance_%=1%, Value2=0.1W, Value_Code=787R, ValueDisplayed=787
R5 R6 R7 R8: library part CMP-0020554-3, "RES, 470 k, 5%, 0.125 W, AEC-Q200 Grade 0, 0805", Manufacturer=Vishay-Dale, Power_W=125mW, Supplier Part Number 1=541-470KACT-ND, TempCo="200 ppm/C", Tolerance_%=5%, Value2=0.125W, Value_Code=470k
R9: library part CMP-0016010-3, "RES, 8.2 k, 5%, 1 W, AEC-Q200 Grade 0, 2512", Manufacturer=Vishay-Dale, Power_W=1W, Supplier Part Number 1=541-8.2KXCT-ND, TempCo="200 ppm/C", Tolerance_%=5%, Value_Code=8k20, ValueDisplayed=8.2k
R10: library part CMP-0021872-2, "RES, 1.21, 1%, 0.125 W, 0805", Manufacturer="Yageo America", Power_W=125mW, Supplier Part Number 1=311-1.21CRCT-ND, TempCo="200 ppm/C", Tolerance_%=1%, Value2=0.125W, Value_Code=1R21, ValueDisplayed=1.21
R11: library part CMP-0022597-4, "RES, 78.7 k, 1%, 0.1 W, AEC-Q200 Grade 0, 0603", Manufacturer=Vishay-Dale, Power_W=100mW, Supplier Part Number 1=541-78.7KHCT-ND, TempCo="100 ppm/C", Tolerance_%=1%, Value2=0.1W, Value_Code=78k7, ValueDisplayed=78.7k
R12: library part CMP-0022449-4, "RES, 4.02 k, 1%, 0.1 W, AEC-Q200 Grade 0, 0603", Manufacturer=Vishay-Dale, Power_W=100mW, Supplier Part Number 1=541-4.02KHCT-ND, TempCo="100 ppm/C", Tolerance_%=1%, Value2=0.1W, Value_Code=4k02, ValueDisplayed=4.02k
